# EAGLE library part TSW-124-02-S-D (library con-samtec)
THROUGH-HOLE .025" SQ POST HEADER Source: Samtec TSW.pdf
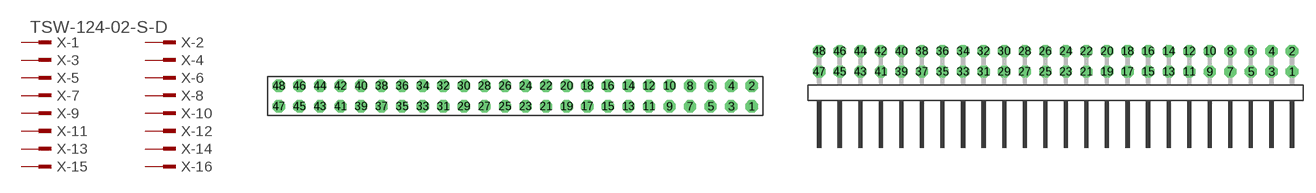
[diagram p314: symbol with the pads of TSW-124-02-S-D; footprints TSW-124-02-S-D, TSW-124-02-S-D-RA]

Designator prefix X; gates -1=MPINV -2=MPIN -3=MPIN -4=MPIN -5=MPIN -6=MPIN -7=MPIN -8=MPIN -9=MPIN -10=MPIN -11=MPIN -12=MPIN -13=MPIN -14=MPIN -15=MPIN -16=MPIN -17=MPIN -18=MPIN -19=MPIN -20=MPIN -21=MPIN -22=MPIN -23=MPIN -24=MPIN -25=MPIN -26=MPIN -27=MPIN -28=MPIN -29=MPIN -30=MPIN -31=MPIN -32=MPIN -33=MPIN -34=MPIN -35=MPIN -36=MPIN -37=MPIN -38=MPIN -39=MPIN -40=MPIN -41=MPIN -42=MPIN -43=MPIN -44=MPIN -45=MPIN -46=MPIN -47=MPIN -48=MPIN

## TSW-124-02-S-D (OC_FARNELL: unknown; OC_NEWARK: unknown)  [TSW-124-02-S-D]
1  -1:1  pas
2  -2:1  pas
3  -3:1  pas
4  -4:1  pas
5  -5:1  pas
6  -6:1  pas
7  -7:1  pas
8  -8:1  pas
9  -9:1  pas
10  -10:1  pas
11  -11:1  pas
12  -12:1  pas
13  -13:1  pas
14  -14:1  pas
15  -15:1  pas
16  -16:1  pas
17  -17:1  pas
18  -18:1  pas
19  -19:1  pas
20  -20:1  pas
21  -21:1  pas
22  -22:1  pas
23  -23:1  pas
24  -24:1  pas
25  -25:1  pas
26  -26:1  pas
27  -27:1  pas
28  -28:1  pas
29  -29:1  pas
30  -30:1  pas
31  -31:1  pas
32  -32:1  pas
33  -33:1  pas
34  -34:1  pas
35  -35:1  pas
36  -36:1  pas
37  -37:1  pas
38  -38:1  pas
39  -39:1  pas
40  -40:1  pas
41  -41:1  pas
42  -42:1  pas
43  -43:1  pas
44  -44:1  pas
45  -45:1  pas
46  -46:1  pas
47  -47:1  pas
48  -48:1  pas

## TSW-124-02-S-D-RA (OC_FARNELL: unknown; OC_NEWARK: unknown)  [TSW-124-02-S-D-RA]
Pads as for TSW-124-02-S-D

## Footprint TSW-124-02-S-D (pad centres in mm)
THROUGH-HOLE .025" SQ POST HEADER Source: Samtec TSW.pdf
drill 1 pad 1.5 octagon: 1 29.21,-1.27; 2 29.21,1.27; 3 26.67,-1.27; 4 26.67,1.27; 5 24.13,-1.27; 6 24.13,1.27; 7 21.59,-1.27; 8 21.59,1.27; 9 19.05,-1.27; 10 19.05,1.27; 11 16.51,-1.27; 12 16.51,1.27; 13 13.97,-1.27; 14 13.97,1.27; 15 11.43,-1.27; 16 11.43,1.27; 17 8.89,-1.27; 18 8.89,1.27; 19 6.35,-1.27; 20 6.35,1.27; 21 3.81,-1.27; 22 3.81,1.27; 23 1.27,-1.27; 24 1.27,1.27; 25 -1.27,-1.27; 26 -1.27,1.27; 27 -3.81,-1.27; 28 -3.81,1.27; 29 -6.35,-1.27; 30 -6.35,1.27; 31 -8.89,-1.27; 32 -8.89,1.27; 33 -11.43,-1.27; 34 -11.43,1.27; 35 -13.97,-1.27; 36 -13.97,1.27; 37 -16.51,-1.27; 38 -16.51,1.27; 39 -19.05,-1.27; 40 -19.05,1.27; 41 -21.59,-1.27; 42 -21.59,1.27; 43 -24.13,-1.27; 44 -24.13,1.27; 45 -26.67,-1.27; 46 -26.67,1.27; 47 -29.21,-1.27; 48 -29.21,1.27

## Footprint TSW-124-02-S-D-RA (pad centres in mm)
THROUGH-HOLE .025" SQ POST HEADER Source: Samtec TSW.pdf
drill 1 pad 1.5 octagon: 1 29.21,1.524; 2 29.21,4.064; 3 26.67,1.524; 4 26.67,4.064; 5 24.13,1.524; 6 24.13,4.064; 7 21.59,1.524; 8 21.59,4.064; 9 19.05,1.524; 10 19.05,4.064; 11 16.51,1.524; 12 16.51,4.064; 13 13.97,1.524; 14 13.97,4.064; 15 11.43,1.524; 16 11.43,4.064; 17 8.89,1.524; 18 8.89,4.064; 19 6.35,1.524; 20 6.35,4.064; 21 3.81,1.524; 22 3.81,4.064; 23 1.27,1.524; 24 1.27,4.064; 25 -1.27,1.524; 26 -1.27,4.064; 27 -3.81,1.524; 28 -3.81,4.064; 29 -6.35,1.524; 30 -6.35,4.064; 31 -8.89,1.524; 32 -8.89,4.064; 33 -11.43,1.524; 34 -11.43,4.064; 35 -13.97,1.524; 36 -13.97,4.064; 37 -16.51,1.524; 38 -16.51,4.064; 39 -19.05,1.524; 40 -19.05,4.064; 41 -21.59,1.524; 42 -21.59,4.064; 43 -24.13,1.524; 44 -24.13,4.064; 45 -26.67,1.524; 46 -26.67,4.064; 47 -29.21,1.524; 48 -29.21,4.064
